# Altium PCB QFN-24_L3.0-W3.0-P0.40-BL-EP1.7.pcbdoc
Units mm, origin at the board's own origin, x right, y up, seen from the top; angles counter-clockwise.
Board outline 16.5 x 17 mm, 2 copper layers (Top Layer, Bottom Layer), stack 0 mm thick; 1 components, 0 nets, 25 pads, 0 vias.
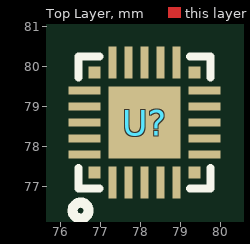
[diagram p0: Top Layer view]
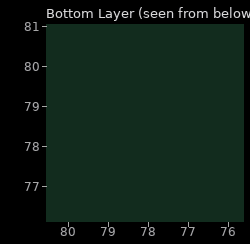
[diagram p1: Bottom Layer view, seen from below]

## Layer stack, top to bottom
Top Layer: signal copper (thickness not stored)
Bottom Layer: signal copper (thickness not stored)

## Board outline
86.35,69.85 69.85,69.85 69.85,86.85 86.35,86.85

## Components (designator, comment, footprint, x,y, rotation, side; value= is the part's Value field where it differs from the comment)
U? "" QFN-24_L3.0-W3.0-P0.40-BL-EP1.7 78.1,78.6 r0 top

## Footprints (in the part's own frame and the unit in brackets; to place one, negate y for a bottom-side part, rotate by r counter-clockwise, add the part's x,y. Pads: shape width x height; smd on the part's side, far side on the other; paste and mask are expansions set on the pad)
QFN-24_L3.0-W3.0-P0.40-BL-EP1.7 [mm]
  rect 0.3x0.3 smd paste-100 mask+0.051: 1(-1.25,-1.25) 7(1.25,-1.25) 13(1.25,1.25) 19(-1.25,1.25)
  rect 0.2x0.8 smd paste-100 mask+0.051: 2(-0.8,-1.5) 3(-0.4,-1.5) 4(0,-1.5) 5(0.4,-1.5) 6(0.8,-1.5) 14(0.8,1.5) 15(0.4,1.5) 16(0,1.5) 17(-0.4,1.5) 18(-0.8,1.5)
  rect 0.8x0.2 smd paste-100 mask+0.051: 8(1.5,-0.8) 9(1.5,-0.4) 10(1.5,0) 11(1.5,0.4) 12(1.5,0.8) 20(-1.5,0.8) 21(-1.5,0.4) 22(-1.5,0) 23(-1.5,-0.4) 24(-1.5,-0.8)
  rect 1.8x1.8 smd paste-100 mask+0.051: 25(0,0)
  silkscreen extent -1.8,-2.4 1.65,1.65

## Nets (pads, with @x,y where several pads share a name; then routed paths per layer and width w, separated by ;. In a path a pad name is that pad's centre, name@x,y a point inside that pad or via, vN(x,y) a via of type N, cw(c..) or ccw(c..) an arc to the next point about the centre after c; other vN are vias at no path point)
pads on no net: U?.1 U?.2 U?.3 U?.4 U?.5 U?.6 U?.7 U?.8 U?.9 U?.10 U?.11 U?.12 U?.13 U?.14 U?.15 U?.16 U?.17 U?.18 U?.19 U?.20 U?.21 U?.22 U?.23 U?.24 U?.25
